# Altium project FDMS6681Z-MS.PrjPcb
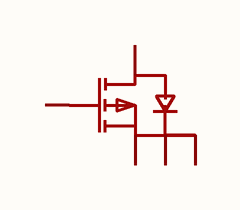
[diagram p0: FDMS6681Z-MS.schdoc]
1 sheet, 1 parts. Net scope: global (net labels, ports and power ports of the same name join across sheets).

## Sheet FDMS6681Z-MS.schdoc
size 127 x 101 mm

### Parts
Q?  fdms6681z-ms  [TDSON-8_L5.9-W5.2-P1.27-BL-1]  (value not drawn)

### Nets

Not connected (* = marked no-connect by the designer): Q? 1(S) 2(S) 3(S) 4(G) 5(D)

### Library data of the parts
Q? = fdms6681z-ms: 数量:1个P沟道;漏源电压(Vdss):30V;连续漏极电流(Id):100A;导通电阻(RDS(on)):3mΩ@10V;耗散功率(Pd):120W;阈值电压(Vgs(th)):1.2V;; Manufacturer: MSKSEMI(美森科); AddInBom: yes; ModelId: 6d3ef2b64d5a4f2dbd2ee02e0c7053d2; ModelTransform: 205.511,242.1255,0,0,0,0,0,42.913,0; Number: 1个P沟道; Drain to Source Voltage: 30V; Current - Continuous Drain(Id): 100A; Pd - Power Dissipation: 120W; Gate Threshold Voltage (Vgs(th)): 1.2V; Gate Charge(Qg): 60nC; Input Capacitance(Ciss): 3.45nF; Reverse Transfer Capacitance (Crss@Vds): 140pF; Type: P沟道; Output Capacitance(Coss): 255pF; Vgs: ±20V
